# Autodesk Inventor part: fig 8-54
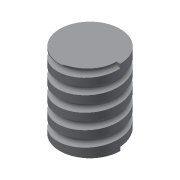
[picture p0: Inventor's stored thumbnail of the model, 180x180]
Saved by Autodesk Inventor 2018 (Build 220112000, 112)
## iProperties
Shininess: 77.0
Length Units: 11269
Angle Units: 11279
Time Units: 11290
Mass Units: 11283
Length Display Precision: 3
Angle Display Precision: 2
Created: 2002-01
Part Number: fig 8-54
Document SubType Name: Modeling
Designer: CADSoft
Density: 1 g/cm^3
Material: Generic
Appearance: Default
Density: 0.0
Volumn: 0.0
Area: 0.0
PropertySet Name: Model Information
Control State: 0
Master: False
Checked Out: False
Author: CADSoft
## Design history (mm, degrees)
sketch "Sketch4"
  geometry: C1 r 20 at (0, 0)
  constraints: 1 centre point
  dimensions: "d44" = 40 diameter of C1
sketch "Sketch2"
  geometry: C1 r 2.5 at (-20, -0.092); 1 further point
  constraints: 1 centre point, 1 other
  dimensions: "d0" = 5 diameter of C1; "d43" = 20 horizontal distance of C1.centre point (0, 0)
extrude "Extrusion2" join sketch "Sketch4" distance "d45" = 50; taper "d46" = 0 deg
coil "Coil6" pitch "d47" = 10; turns "d49" = 5; dims "d48" = 10, "d50" = 0, angle "d51" = 90 deg, angle "d52" = 90 deg, "d53" = 0, "d54" = 0
body "Solid1"
